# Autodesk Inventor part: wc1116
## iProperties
Shininess: 64.0
Length Units: 11272
Angle Units: 11279
Time Units: 11290
Mass Units: 11286
Length Display Precision: 3
Angle Display Precision: 2
Compacted: True
Part Number: wc1116
Document SubType Name: Modeling
Created: 2004-08
Designer: John Blackburn
Manufacturer: Standard
Standards Organization: Custom
Density: 0.0
Volumn: 0.0
Area: 0.0
PropertySet Name: Model Information
Control State: 0
Master: False
Checked Out: False
Author: John Blackburn
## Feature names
1. Base1
